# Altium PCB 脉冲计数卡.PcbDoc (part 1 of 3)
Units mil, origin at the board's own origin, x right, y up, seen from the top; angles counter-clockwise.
Board outline 5137.66 x 6771.53 mil, 4 copper layers (Top Layer, GND, VCC, Bottom Layer); 160 components, 225 nets, 1035 pads, 287 vias.
Unrouted connection lines stored in the file: 61.
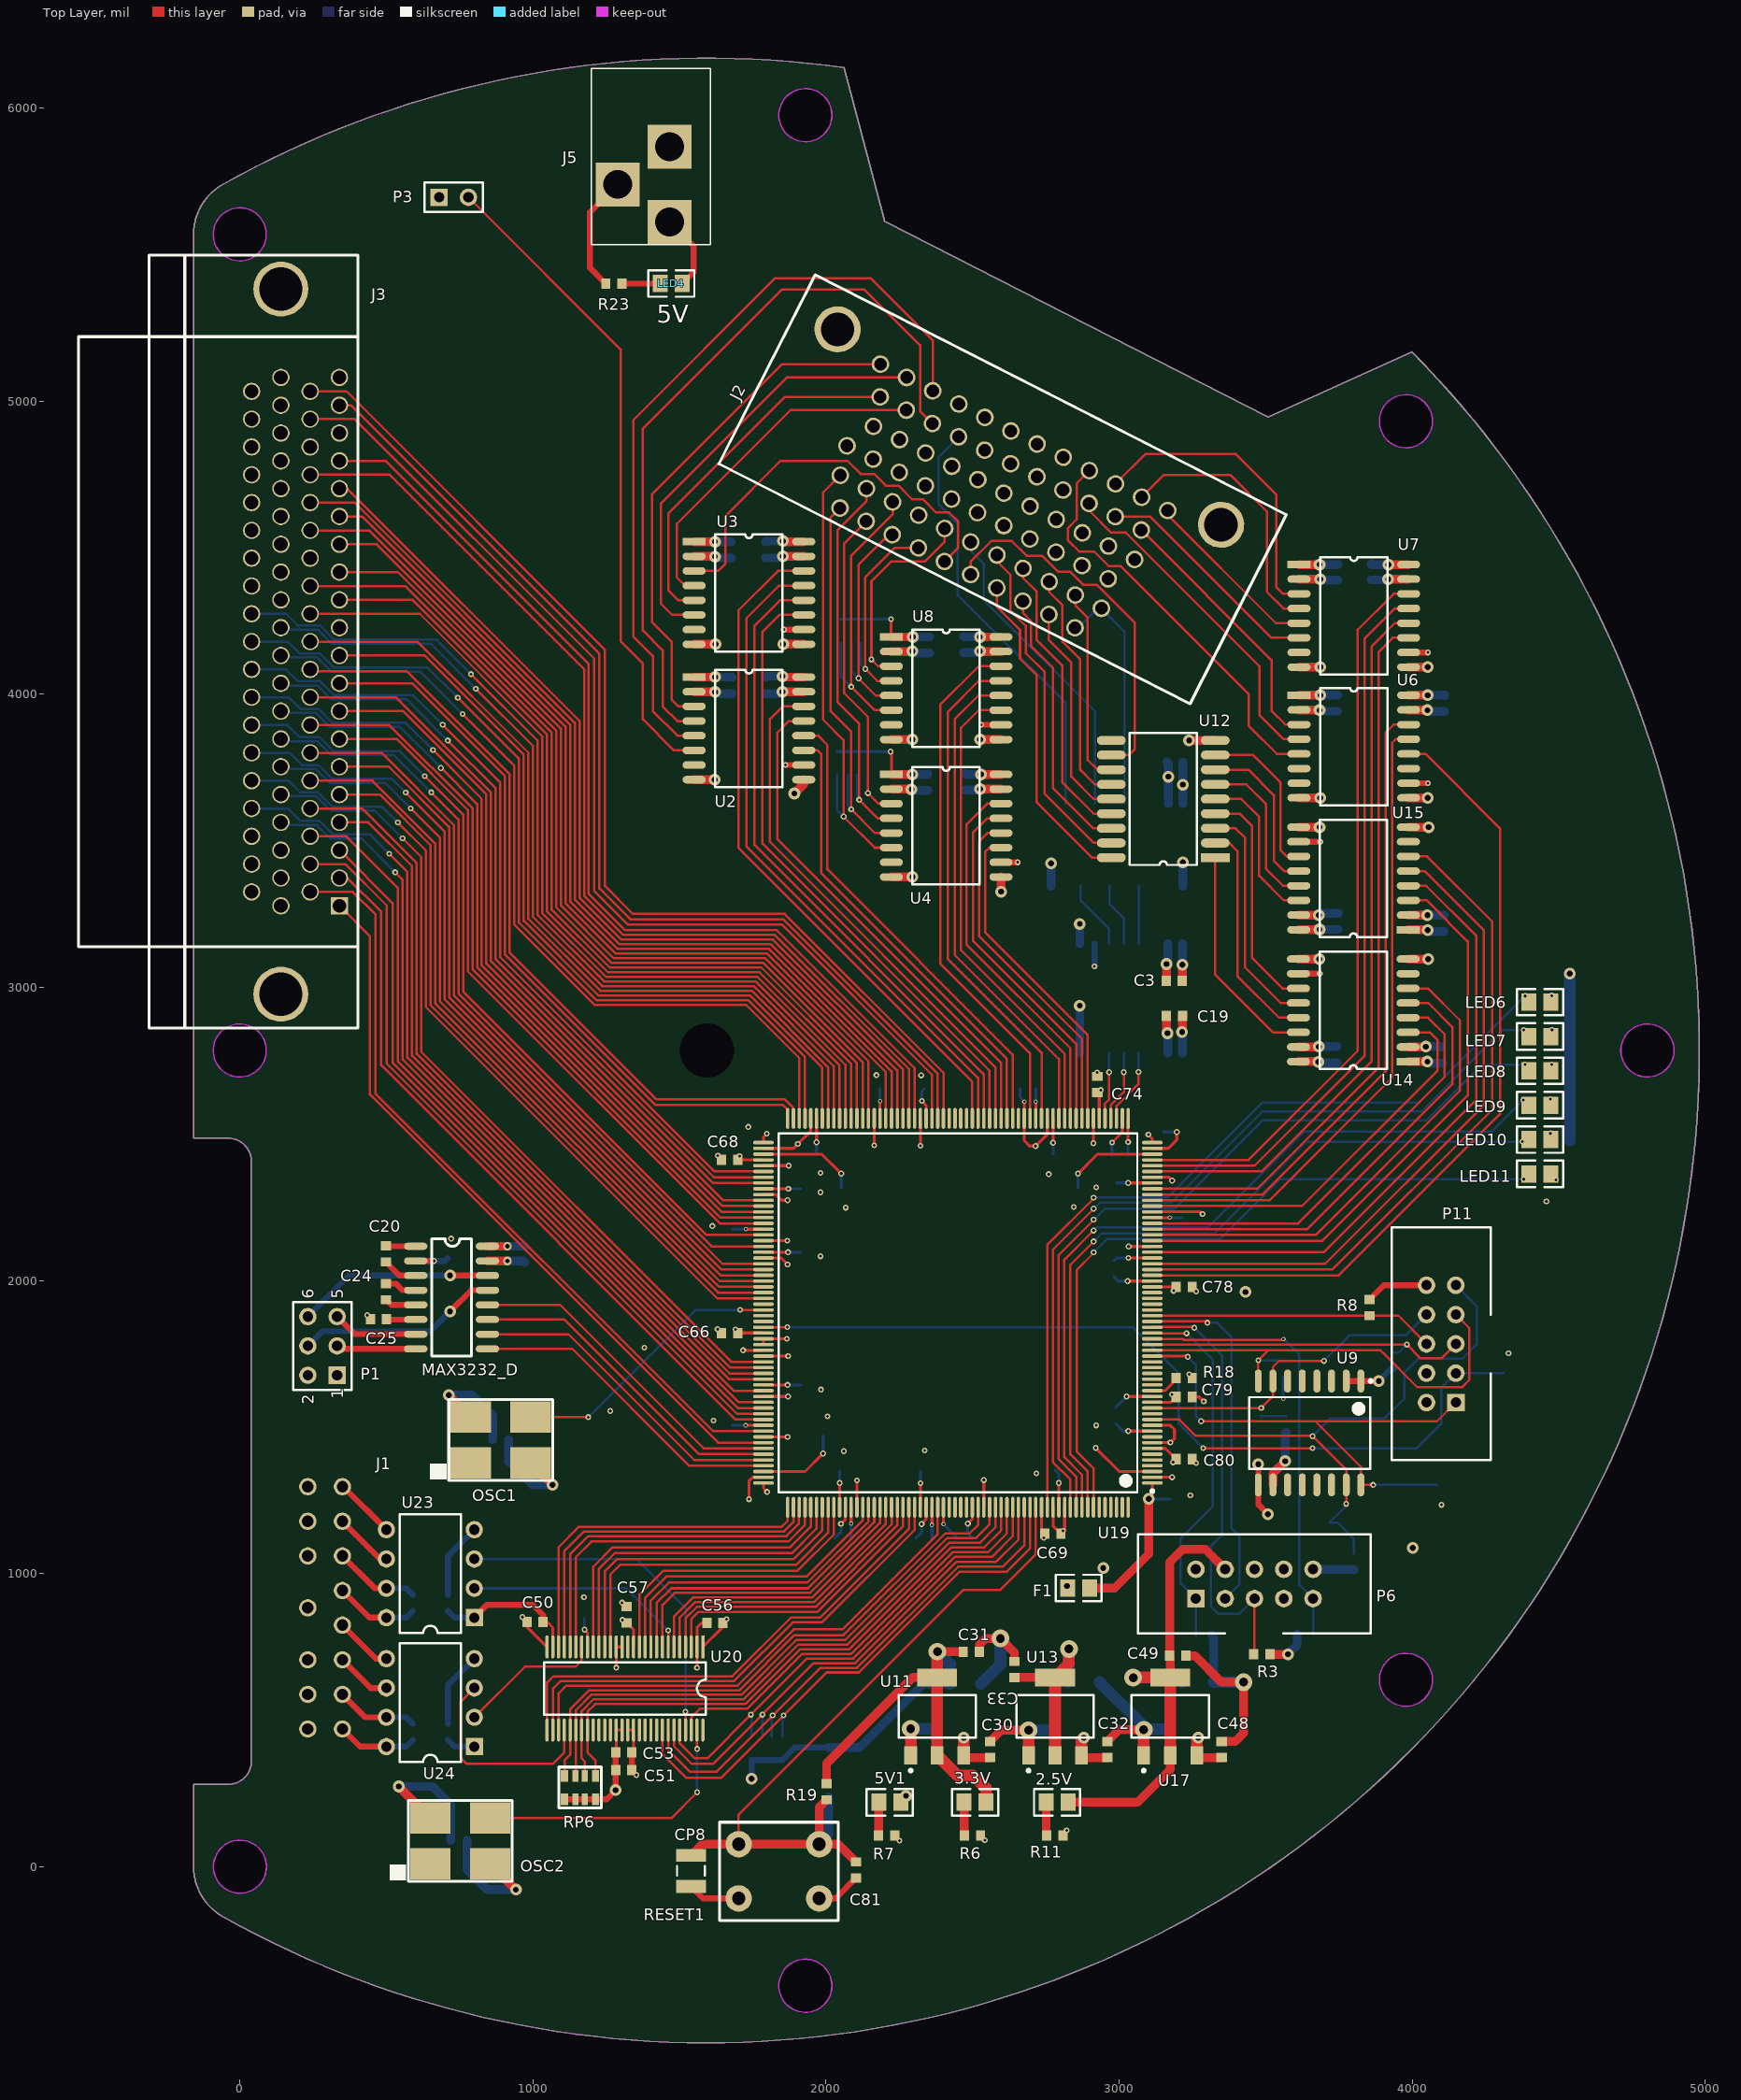
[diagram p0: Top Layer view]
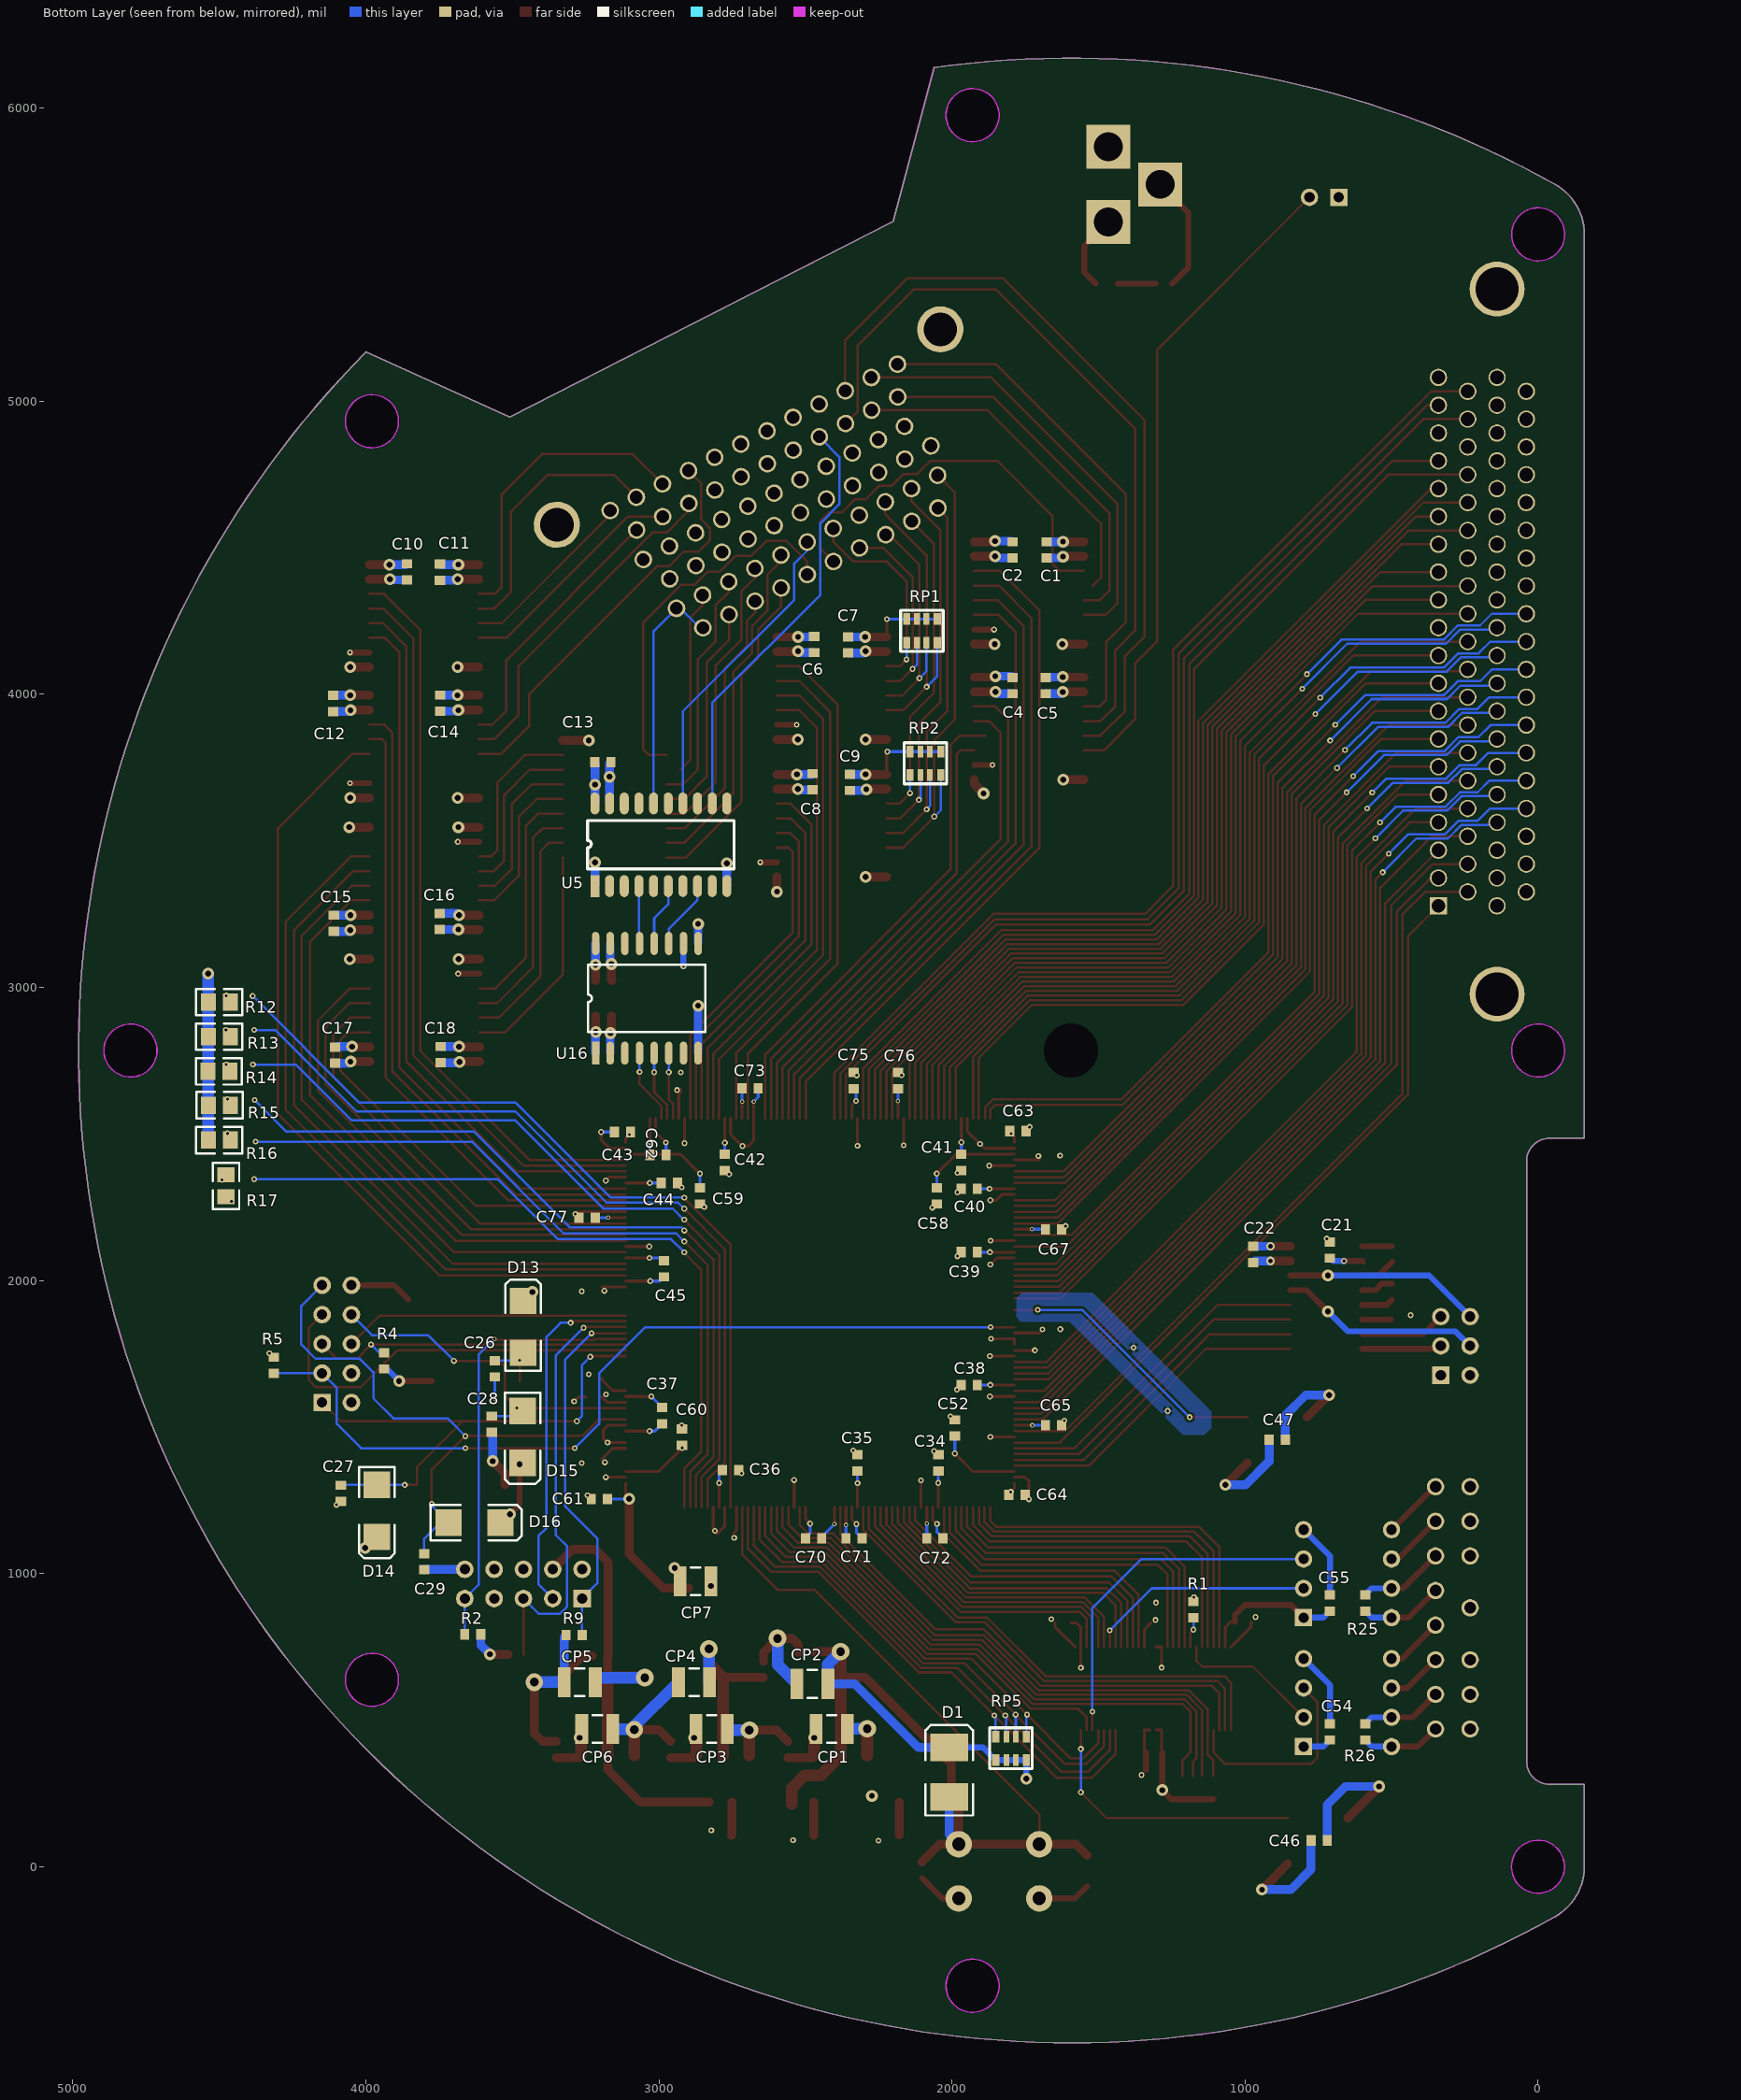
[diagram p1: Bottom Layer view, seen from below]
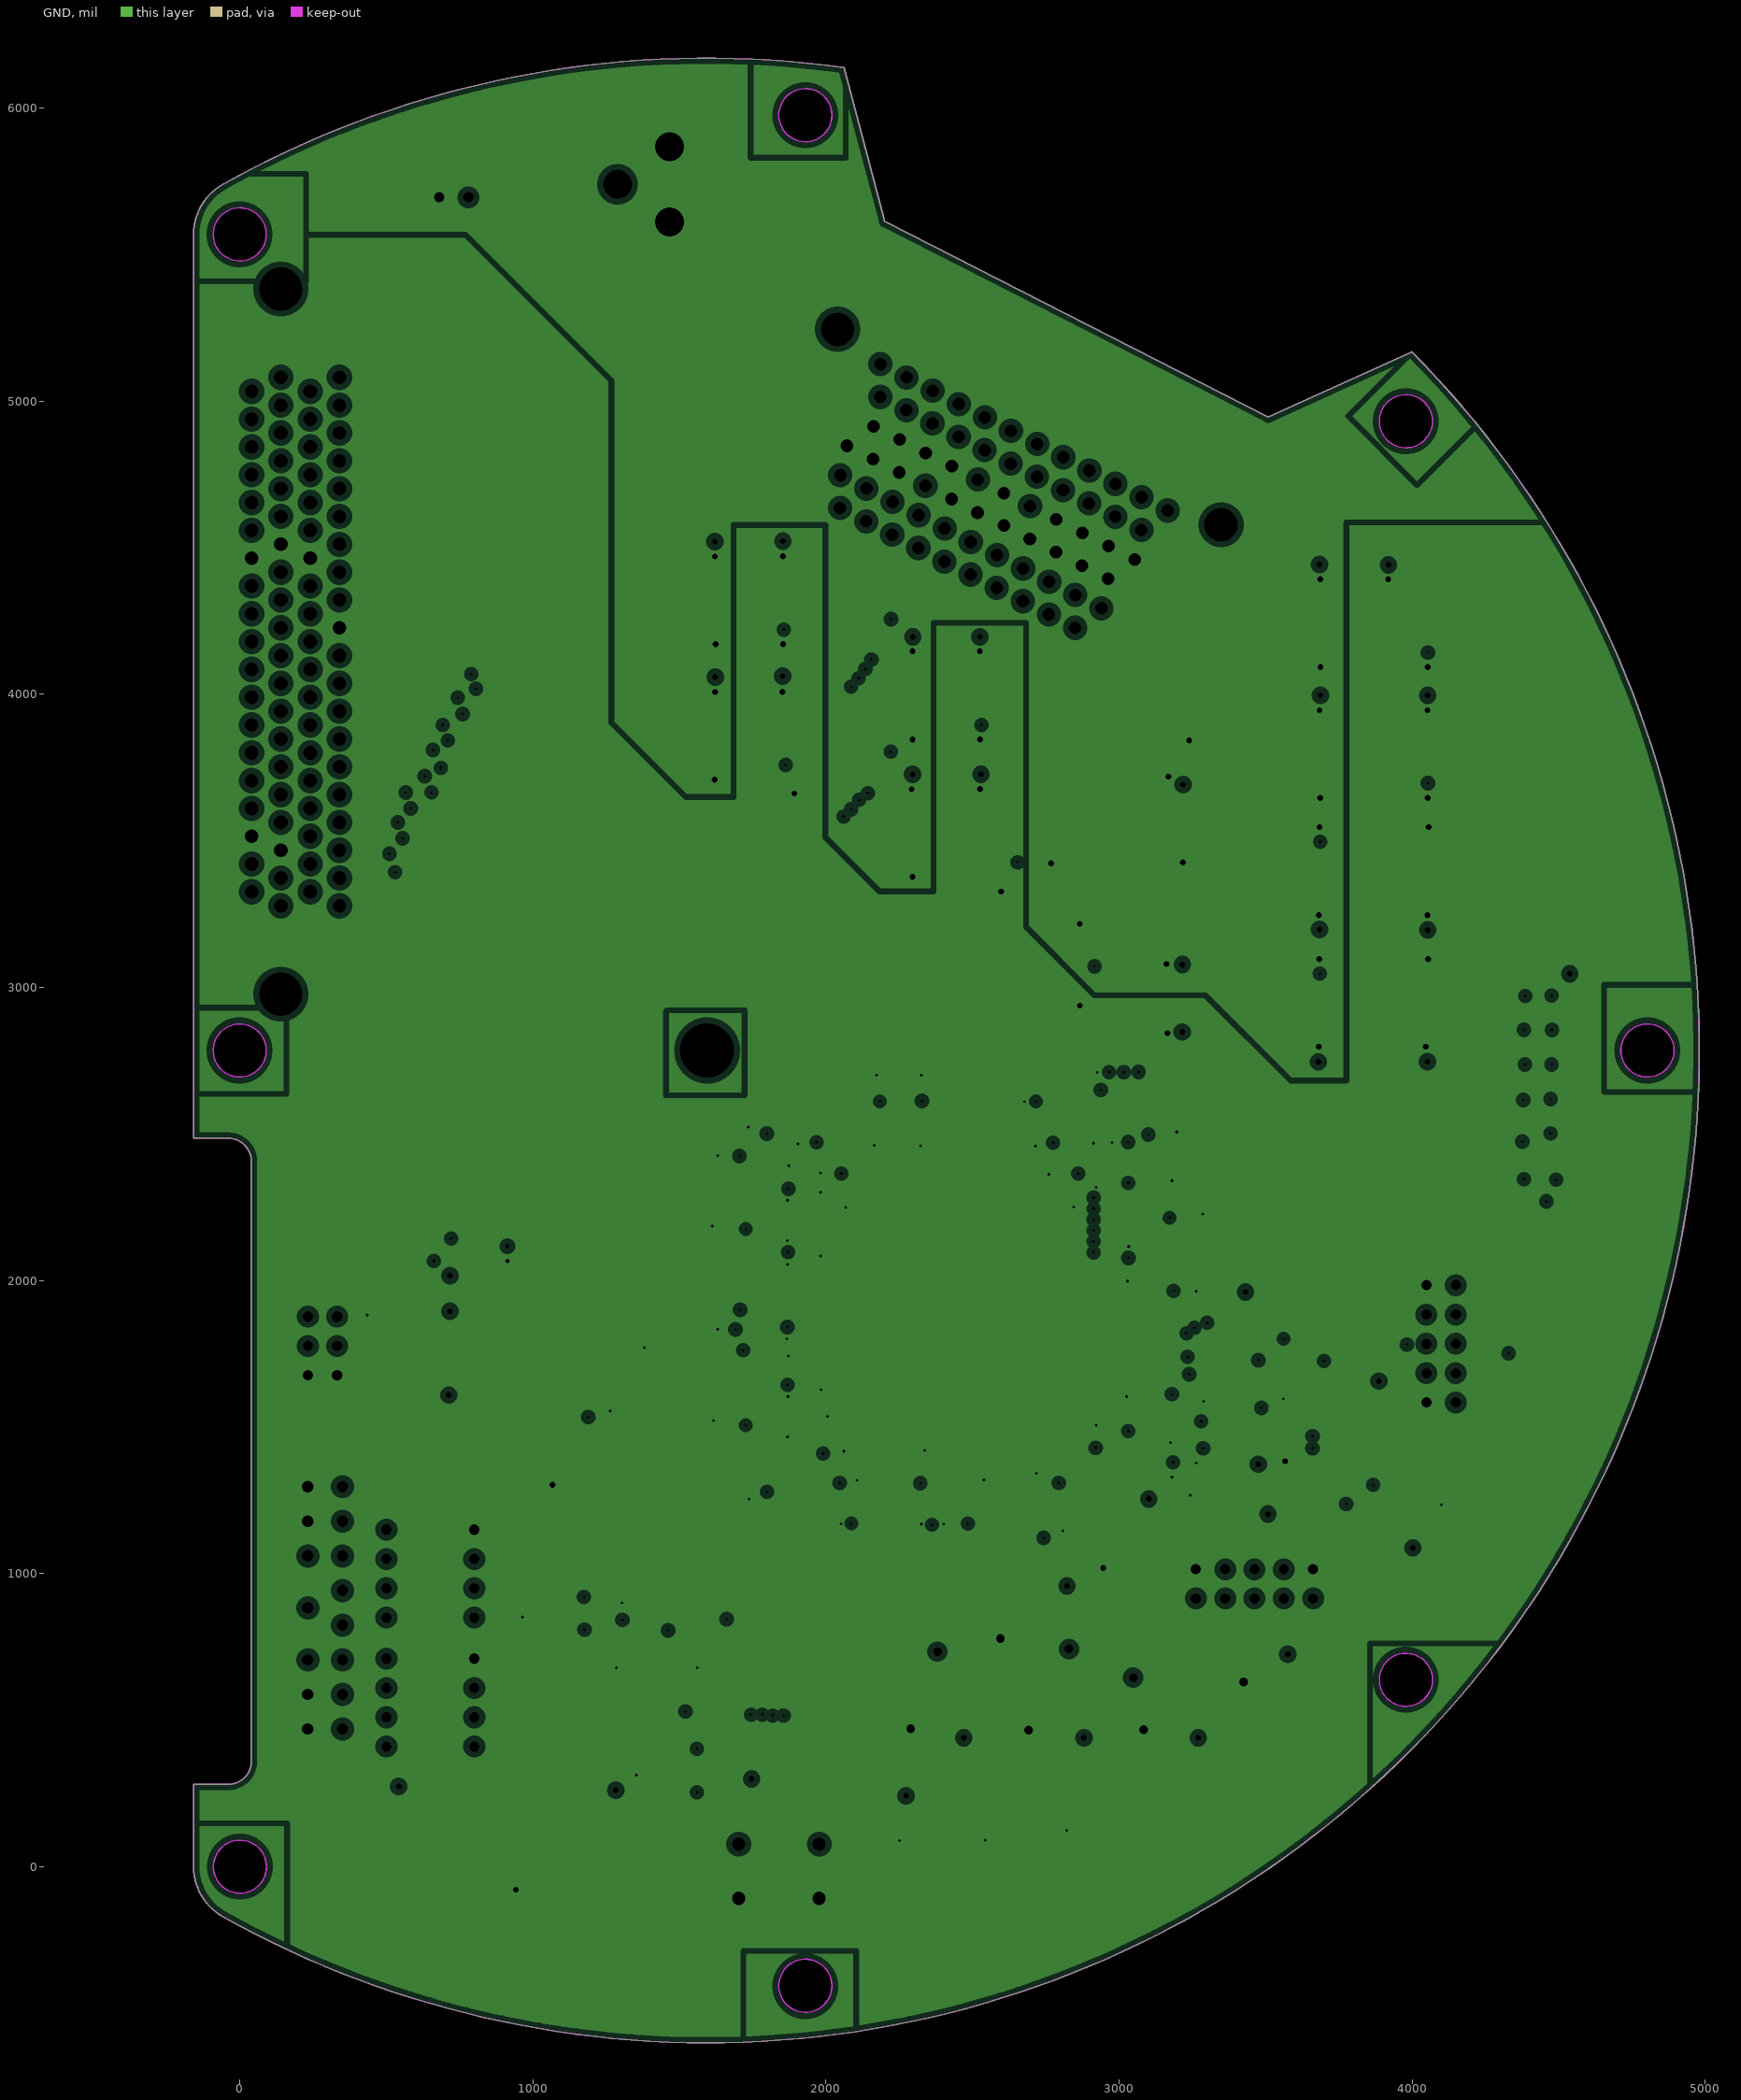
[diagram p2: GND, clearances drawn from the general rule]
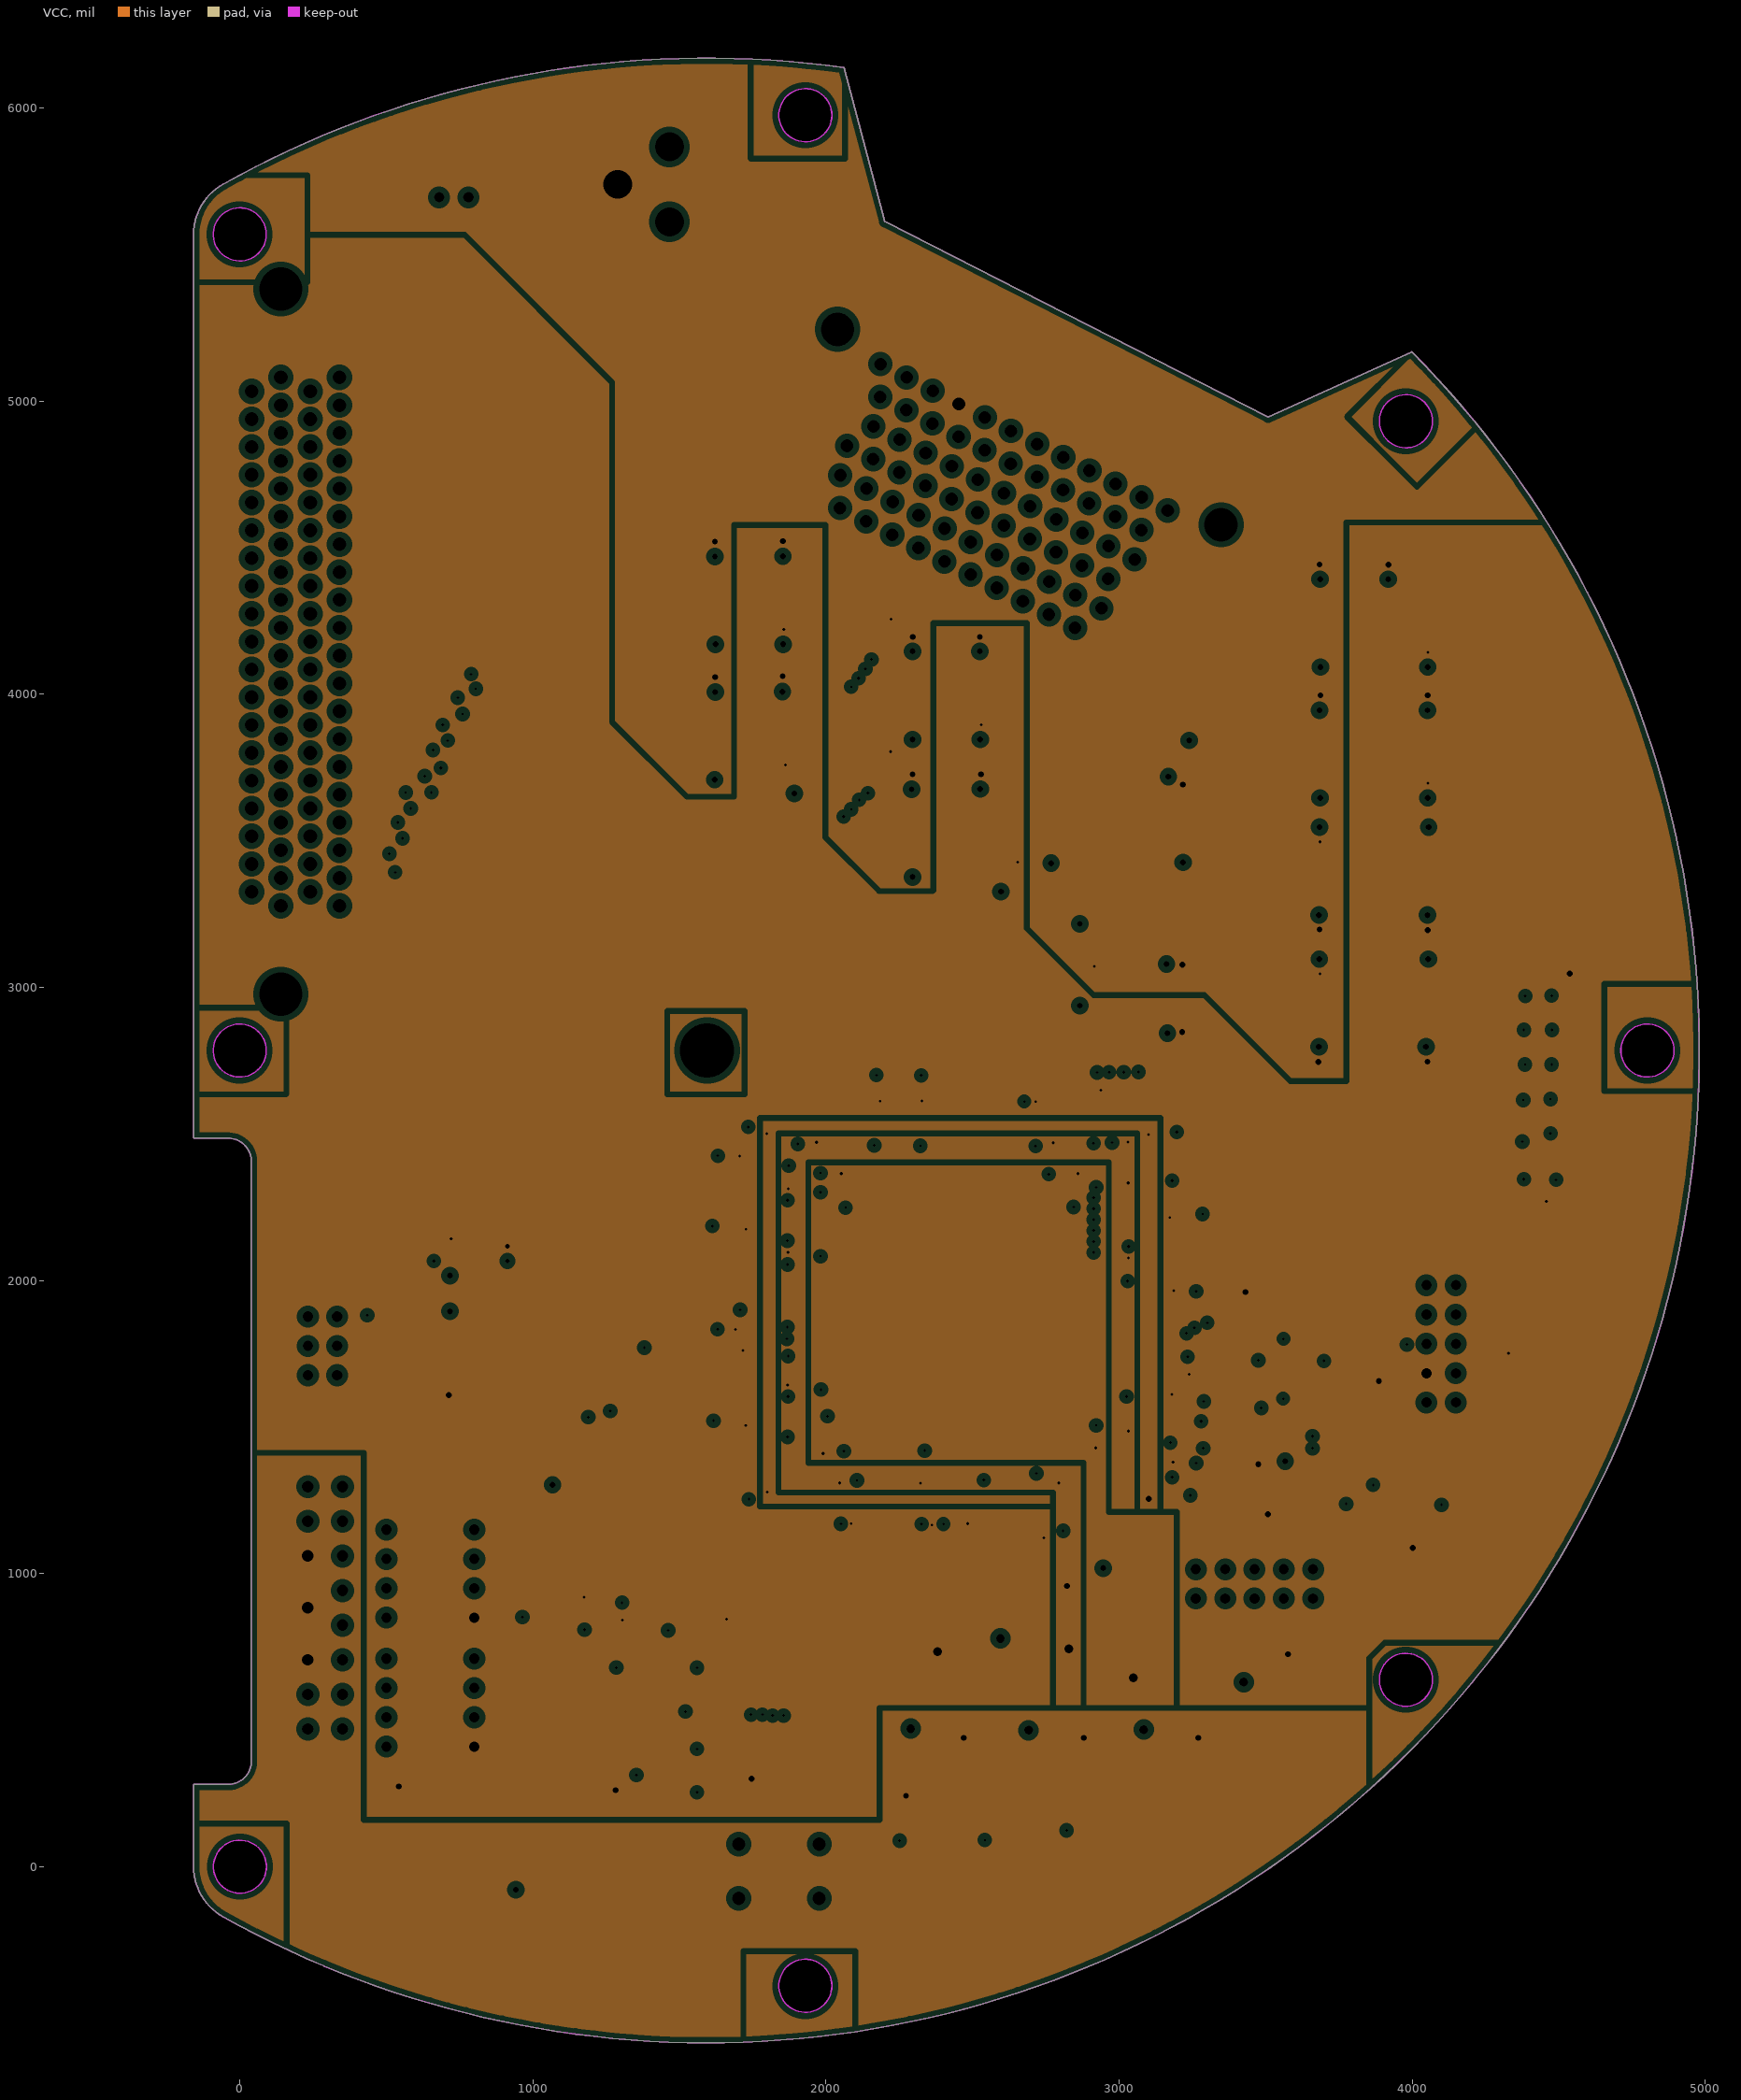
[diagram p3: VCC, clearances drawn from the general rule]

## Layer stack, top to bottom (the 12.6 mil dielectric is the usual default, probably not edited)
Top Layer: signal copper 1.4
Dielectric: core 12.6, FR-4, Dk 4.8
GND: plane copper 1.4, net (Multiple Nets)
Dielectric: prepreg 12.6, FR-4, Dk 4.8
VCC: plane copper 1.4, net (Multiple Nets)
Dielectric: core 12.6, FR-4, Dk 4.8
Bottom Layer: signal copper 1.4

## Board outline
-157.86,0.86 -157.86,281.01 -39.75,281.01 ccw(c-39.75,359.75) 38.99,359.75 38.99,2407 ccw(c-39.75,2407) -39.75,2485.74 -157.86,2485.74 -157.86,5569.05 cw(c38.99,5569.05) -57,5740.91 -57.03,5740.89 cw(c1594.11,2784.95) 2061.06,6138.43 2061,6138 2201.09,5613.19 2205.35,5610.72 3508.63,4946.67 3508.67,4946.74 3998,5168 3998.66,5168.65 cw(c1594.12,2784.95) -57.02,-170.99 -57,-171 cw(c38.99,0.86)

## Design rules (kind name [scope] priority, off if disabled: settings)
Clearance [All] p1: gap=5
Clearance Clearance_1 [All] p2: gap=7.87
ComponentClearance [All] p1: gap=0 collisioncheckmode=3 verticalgap=0 showdistances=FALSE
FabricationTestPointUsage TestPointUsage [All] p1: valid=0 allowmultiple=FALSE
FabricationTestpoint Testpoint [All] p1: side=3 testpointundercomponent=TRUE minsize=40 maxsize=100 preferedsize=60 minholesize=0 maxholesize=40 preferedholesize=32 testpointgrid=1 allowsidetop=TRUE allowsidebottom=TRUE usegrid=TRUE gridtolerance=0.01
HoleSize [All] p1: absolutevalues=TRUE maxlimit=200 minlimit=1 maxpercent=80.000 minpercent=20.000
PlaneClearance [All] p1: clearance=20
PlaneConnect [All] p1: planeconnectstyle=Direct reliefexpansion=20 reliefentries=4 reliefconductorwidth=10 reliefairgap=10
PolygonConnect [All] p1: connectstyle=Relief reliefconductorwidth=10 reliefentries=4 polygonreliefangle="90 Angle"
RoutingVias [All] p1: holewidth=23.62 width=39.37 viastyle="Through Hole" minholewidth=10 minwidth=20 maxholewidth=40 maxwidth=80
SilkscreenOverComponentPads [All] p1: minsilkscreentomaskgap=10
SolderMaskExpansion [All] p1: expansion=4
Width [All] p1: maxlimit=60 minlimit=5 preferedwidth=8
21 further rules are at their usual default settings.

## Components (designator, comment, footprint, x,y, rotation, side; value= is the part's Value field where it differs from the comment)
2.5V "LED12V" R2012-0805 2788.6,220 r180 top (schematic designator LED5)
3.3V "LED12V" R2012-0805 2508.6,220 r180 top (schematic designator LED2)
5V1 "LED12V" R2012-0805 2217.6,220 r180 top (schematic designator LED1)
C1 "0.1uF" 1608[0603] 1677,4493 r90 bottom
C2 "0.1uF" 1608[0603] 1793,4493 r90 bottom
C3 "0.1uF" 1608[0603] 3188,3023 r0 top
C4 "0.1uF" 1608[0603] 1793,4030 r90 bottom
C5 "0.1uF" 1608[0603] 1680,4030 r90 bottom
C6 "0.1uF" 1608[0603] 2470,4170 r90 bottom
C7 "0.1uF" 1608[0603] 2354,4169 r90 bottom
C8 "0.1uF" 1608[0603] 2475,3702 r90 bottom
C9 "0.1uF" 1608[0603] 2348,3700 r90 bottom
C10 "0.1uF" 1608[0603] 3860,4418 r90 bottom
C11 "0.1uF" 1608[0603] 3747,4417 r90 bottom
C12 "0.1uF" 1608[0603] 4111,3969 r90 bottom
C13 "0.1uF" 1608[0603] 3191,3769 r0 bottom
C14 "0.1uF" 1608[0603] 3746,3970 r90 bottom
C15 "0.1uF" 1608[0603] 4109,3219 r270 bottom
C16 "0.1uF" 1608[0603] 3748,3225 r270 bottom
C17 "0.1uF" 1608[0603] 4105,2769 r270 bottom
C18 "0.1uF" 1608[0603] 3744,2771 r270 bottom
C19 "0.1uF" 1608[0603] 3189,2903 r0 top
C20 "104" 1608[0603] 498,2091 r90 top
C21 "104" 1608[0603] 710,2104 r90 bottom
C22 "104" 1608[0603] 972,2089 r90 bottom
C24 "104" 1608[0603] 499,1962 r90 top
C25 "104" 1608[0603] 473,1868 r0 top
C26 "10pF" 1608[0603] 3560,1699 r90 bottom
C27 "10pF" 1608[0603] 4085,1274 r90 bottom
C28 "10pF" 1608[0603] 3570,1510 r90 bottom
C29 "10pF" 1608[0603] 3801,1041 r90 bottom
C30 "0.1uF" 1608[0603] 2560,400 r270 top
C31 "0.1uF" 1608[0603] 2496,733 r180 top
C32 "0.1uF" 1608[0603] 2960,400 r270 top
C33 "0.1uF" 1608[0603] 2643,673 r270 top
C34 "0.1uF" 1608[0603] 2046,1378 r270 bottom
C35 "0.1uF" 1608[0603] 2323,1378 r270 bottom
C36 "0.1uF" 1608[0603] 2755.12,1353 r0 bottom
C37 "0.1uF" 1608[0603] 2989,1539 r270 bottom
C38 "0.1uF" 1608[0603] 1941,1644 r180 bottom
C39 "0.1uF" 1608[0603] 1941,2097 r180 bottom
C40 "0.1uF" 1608[0603] 1941,2313 r180 bottom
C41 "0.1uF" 1608[0603] 1968,2403 r90 bottom
C42 "0.1uF" 1608[0603] 2775,2403 r90 bottom
C43 "0.1uF" 1608[0603] 3003,2428.59 r0 bottom
C44 "0.1uF" 1608[0603] 2964,2333 r0 bottom
C45 "0.1uF" 1608[0603] 2983,2040 r90 bottom
C46 "0.1uF" 1608[0603] 747,90 r0 bottom
C47 "0.1uF" 1608[0603] 890,1457 r0 bottom
C48 "0.1uF" 1608[0603] 3350,400 r270 top
C49 "0.1uF" 1608[0603] 3200,720 r180 top
C50 "0.1uF" 1608[0603] 1007,835 r0 top
C51 "0.1uF" 1608[0603] 1310,330 r180 top
C52 "0.1uF" 1608[0603] 1990,1497 r270 bottom
C53 "0.1uF" 1608[0603] 1310,390 r180 top
C54 "0.1uF" 1608[0603] 710,460 r90 bottom
C55 "0.1uF" 1608[0603] 710,900 r90 bottom
C56 "0.1uF" 1608[0603] 1621,832 r0 top
C57 "0.1uF" 1608[0603] 1320,860 r90 top
C58 "0.1uF" 1608[0603] 2052,2289 r90 bottom
C59 "0.1uF" 1608[0603] 2860,2289 r90 bottom
C60 "0.1uF" 1608[0603] 2921,1466 r270 bottom
C61 "0.1uF" 1608[0603] 3203,1254 r180 bottom
C62 "0.1uF" 1608[0603] 3124,2507 r180 bottom
C63 "0.1uF" 1608[0603] 1775,2510 r0 bottom
C64 "0.1uF" 1608[0603] 1778,1269 r0 bottom
C65 "0.1uF" 1608[0603] 1653,1506 r0 bottom
C66 "0.1uF" 1608[0603] 1671,1821 r0 top
C67 "0.1uF" 1608[0603] 1653,2175 r0 bottom
C68 "0.1uF" 1608[0603] 1671,2412 r0 top
C69 "0.1uF" 1608[0603] 2774,1136 r180 top
C70 "0.1uF" 1608[0603] 2472,1121 r0 bottom
C71 "0.1uF" 1608[0603] 2334,1121 r0 bottom
C72 "0.1uF" 1608[0603] 2058,1121 r0 bottom
C73 "0.1uF" 1608[0603] 2689,2656.41 r0 bottom
C74 "0.1uF" 1608[0603] 2926,2669 r270 top
C75 "0.1uF" 1608[0603] 2335,2682 r270 bottom
C76 "0.1uF" 1608[0603] 2184,2682 r270 bottom
C77 "0.1uF" 1608[0603] 3245,2214 r180 bottom
C78 "0.1uF" 1608[0603] 3222,1978 r180 top
C79 "0.1uF" 1608[0603] 3222,1603 r180 top
C80 "0.1uF" 1608[0603] 3222,1391 r180 top
C81 "0.1uF" 1608[0603] 2102,-11 r90 top
CP1 "10uF" C1210 2410,470 r180 bottom
CP2 "10uF" C1210 2476,624 r0 bottom
CP3 "10uF" C1210 2820,470 r180 bottom
CP4 "10uF" C1210 2880,630 r0 bottom
CP5 "10uF" C1210 3210,470 r180 bottom
CP6 "10uF" C1210 3270,630 r0 bottom
CP7 "22uF" C1210 2875,974 r0 bottom
CP8 "22uF" C1210 1539,-14 r270 top
D1 "Diode" DSO-C2/X3.3 2009,375 r90 bottom
D13 "D Schottky" SMB 3463,1842 r90 bottom
D14 "D Schottky" SMB 3962,1214 r270 bottom
D15 "D Schottky" SMB 3465,1467 r270 bottom
D16 "D Schottky" SMB 3629,1174 r180 bottom
F1 "Fuse" R2012-0805 2862,951 r180 top
J1 "J29J-15" J29J-15 350,470 r90 top locked
J2 "J30JZKW66" J30J-66ZKW2 2630,4787 r153 top locked
J3 "DB78" DB78 240,4180 r0 top locked
J5 "Header 3" POWER_CON 1466,5612 r90 top
LED4 "LED12V" R2012-0805 1472,5402 r0 top
LED6 "LED12V" R2012-0805 4436,2950 r180 top
LED7 "LED12V" R2012-0805 4436,2832.8 r180 top
LED8 "LED12V" R2012-0805 4436,2715.6 r180 top
LED9 "LED12V" R2012-0805 4436,2598.4 r180 top
LED10 "LED12V" R2012-0805 4436,2481.2 r180 top
LED11 "LED12V" R2012-0805 4436,2364 r180 top
MAX3232_D "SP3232E" SOJ-16_2 600,2117 r0 top locked
OSC1 "CRYSTAL  40M" OSC 788,1378 r0 top
OSC2 "CRYSTAL  32M" OSC 650,10 r0 top
P1 "Header 3X2" HDR2X3 332,1677 r90 top locked
P3 "Header 2" HDR1X2 680,5696 r0 top locked
P6 "Header 5X2" FPGA_LOAD 3262,915 r0 top locked
P11 "Header 5X2" FPGA_LOAD 4149,1584 r90 top locked
R1 "10K" 1608[0603] 1176,877 r270 bottom
R2 "10K" 1608[0603] 3635,793 r180 bottom
R3 "10K" 1608[0603] 3487,725 r0 top
R4 "10K" 1608[0603] 3937,1726 r270 bottom
R5 "10K" 1608[0603] 4314,1711 r90 bottom
R6 "1K" 1608[0603] 2499.6,107 r0 top
R7 "1K" 1608[0603] 2206.6,107 r0 top
R8 "10K" 1608[0603] 3855,1908 r270 top
R9 "1K" 1608[0603] 3289,790 r180 bottom
R11 "1K" 1608[0603] 2780.6,107 r0 top
R12 "1K" R2012-0805 4500,2950 r0 bottom
R13 "1K" R2012-0805 4500,2832 r0 bottom
R14 "1K" R2012-0805 4501,2714 r0 bottom
R15 "1K" R2012-0805 4499,2598 r0 bottom
R16 "1K" R2012-0805 4500,2479 r0 bottom
R17 "1K" R2012-0805 4477,2323 r270 bottom
R18 "10K" 1608[0603] 3222,1668 r180 top
R19 "1K" 1608[0603] 2002,256 r90 top
R23 "1K" 1608[0603] 1276,5401 r180 top
R25 "120" 1608[0603] 590,900 r90 bottom
R26 "120" 1608[0603] 590,460 r90 bottom
RESET1 "SW" SW4 1702,-8 r90 top
RP1 "1K" RP8 2055,4257 r270 bottom
RP2 "1K" RP8 2043,3805 r270 bottom
RP5 "470" RP8 1846,364 r90 bottom
RP6 "470" RP8 1113,230 r90 top
U2 "SI4880" RW-16 1550,4059 r0 top locked
U3 "SI4880" RW-16 1550,4521 r0 top locked
U4 "SI4880" RW-16 2223,3727 r0 top locked
U5 "SN74ABT244AN" SN74ABT244ADW--SOIC20 3218,3287 r90 bottom locked
U6 "SI4880" RW-16 3614,3997 r0 top locked
U7 "SI4880" RW-16 3614,4443 r0 top locked
U8 "SI4880" RW-16 2223,4196 r0 top locked
U9 "EPCS16SI16N" SOIC16_L 3650,1480 r270 top locked
U11 "REG1117" ZZ311 2289,380 r0 top locked
U12 "ULN2803" ULN2803AFWG--SOIC18 3328,3443 r180 top locked
U13 "REG1117" ZZ311 2691,380 r0 top locked
U14 "SI4880" RW-16 3986,2747 r180 top locked
U15 "SI4880" RW-16 3987,3197 r180 top locked
U16 "SI4880" RW-16 3216,2776 r90 bottom locked
U17 "REG1117" ZZ311 3084,380 r0 top locked
U19 "EP3C16Q240C8N" PQFP240_N 2450,1890 r180 top locked
U20 "SC28L202A1DGG" TSSOP56 1580,750 r270 top
U23 "MAX3077EESA" DIP8 650,1000 r90 top locked
U24 "MAX3077EESA" DIP8 650,560 r90 top locked

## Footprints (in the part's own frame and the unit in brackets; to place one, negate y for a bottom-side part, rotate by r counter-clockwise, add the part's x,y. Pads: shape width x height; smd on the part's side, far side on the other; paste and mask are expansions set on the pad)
1608[0603] [mm]
  rect 0.8x0.9 smd: 1(-0.7,0) 2(0.7,0)
  body extent -0.87,-0.48 0.87,0.48, height 1.3
C1210 [mm]
  rect 1.1x2.6 smd: 1(-1.35,0) 2(1.35,0)
  silkscreen extent -0.4,-1.2 0.4,1.2, body extent -1.7,-1.35 1.7,1.35, height 1.3
DB78 [mm]
  rect 1.5x1.5 hole 1.19: 1(2.54,-22.895)
  round 1.5 hole 1.19: 2(0,-21.69) 3(2.54,-20.485) 4(0,-19.28) 5(2.54,-18.075) 6(0,-16.87) 7(2.54,-15.665) 8(0,-14.46) 9(2.54,-13.255) 10(0,-12.05) 11(2.54,-10.845) 12(0,-9.64) 13(2.54,-8.435) 14(0,-7.23) 15(2.54,-6.025) 16(0,-4.82) 17(2.54,-3.615) 18(0,-2.41) 19(2.54,-1.205) 20(0,0) 21(2.54,1.205) 22(0,2.41) 23(2.54,3.615) 24(0,4.82) 25(2.54,6.025) 26(0,7.23) 27(2.54,8.435) 28(0,9.64) 29(2.54,10.845) 30(0,12.05) 31(2.54,13.255) 32(0,14.46) 33(2.54,15.665) 34(0,16.87) 35(2.54,18.075) 36(0,19.28) 37(2.54,20.485) 38(0,21.69) 39(2.54,22.895) 40(-2.54,22.895) 41(-5.08,21.69) 42(-2.54,20.485) 43(-5.08,19.28) 44(-2.54,18.075) 45(-5.08,16.87) 46(-2.54,15.665) 47(-5.08,14.46) 48(-2.54,13.255) 49(-5.08,12.05) 50(-2.54,10.845) 51(-5.08,9.64) 52(-2.54,8.435) 53(-5.08,7.23) 54(-2.54,6.025) 55(-5.08,4.82) 56(-2.54,3.615) 57(-5.08,2.41) 58(-2.54,1.205) 59(-5.08,0) 60(-2.54,-1.205) 61(-5.08,-2.41) 62(-2.54,-3.615) 63(-5.08,-4.82) 64(-2.54,-6.025) 65(-5.08,-7.23) 66(-2.54,-8.435) 67(-5.08,-9.64) 68(-2.54,-10.845) 69(-5.08,-12.05) 70(-2.54,-13.255) 71(-5.08,-14.46) 72(-2.54,-15.665) 73(-5.08,-16.87) 74(-2.54,-18.075) 75(-5.08,-19.28) 76(-2.54,-20.485) 77(-5.08,-21.69) 78(-2.54,-22.895)
  round 4.76 hole 3.75: 79(-2.54,-30.555) 80(-2.54,30.555)
  silkscreen extent -20.07,-33.5 4.13,33.5
DIP8 [mm]
  rect 1.5x1.5 hole 0.9: 1(-3.81,-3.81)
  round 1.5 hole 0.9: 2(-1.27,-3.81) 3(1.27,-3.81) 4(3.81,-3.81) 5(3.81,3.81) 6(1.27,3.81) 7(-1.27,3.81) 8(-3.81,3.81)
  silkscreen extent -5.15,-2.65 5.15,2.65
DSO-C2/X3.3 [mm]
  rect 2.4x3.3 smd: 1(-3.475,0.006) 2(0.808,0.006)
  silkscreen extent -5.07,-2.04 2.76,2.06
FPGA_LOAD [mil]
  rect 60x60 hole 35: 1(0,0)
  round 60 hole 35: 2(0,100) 3(100,0) 4(100,100) 5(200,0) 6(200,100) 7(300,0) 8(300,100) 9(400,0) 10(400,100)
  silkscreen extent -197,-119 597,219
HDR1X2 [mm]
  rect 1.5x1.5 hole 0.9: 1(0,0)
  round 1.5 hole 0.9: 2(2.54,0)
  silkscreen extent -1.27,-1.27 3.81,1.27
HDR2X3 [mm] "Connector; Header; 3x2 Position"
  rect 1.5x1.5 hole 0.9: 1(0,0)
  round 1.5 hole 0.9: 2(0,2.54) 3(2.54,0) 4(2.54,2.54) 5(5.08,0) 6(5.08,2.54)
  silkscreen extent -1.27,-1.27 6.35,3.81
J29J-15 [mm]
  round 1.5 hole 1: 1(0,0) 2(3,0) 3(6,0) 4(9,0) 5(12,0) 6(15,0) 7(18,0) 8(21,0) 9(0,3) 10(3,3) 11(6,3) 12(10.5,3) 13(15,3) 14(18,3) 15(21,3)
J30J-66ZKW2 [mil]
  round 60 hole 43.31: 1(-550,-101) 2(-500,-1) 3(-450,-101) 4(-400,-1) 5(-350,-101) 6(-300,-1) 7(-250,-101) 8(-200,-1) 9(-150,-101) 10(-100,-1) 11(-50,-101) 12(0,0) 13(50,-100) 14(100,-1) 15(150,-101) 16(200,-1) 17(250,-101) 18(300,-1) 19(350,-101) 20(400,-1) 21(450,-101) 22(500,-1) 23(550,-101) 24(-525,99) 25(-475,199) 26(-425,99) 27(-375,199) 28(-325,99) 29(-275,199) 30(-225,99) 31(-175,199) 32(-125,99) 33(-75,199) 34(-25,100) 35(25,200) 36(75,99) 37(125,199) 38(175,99) 39(225,199) 40(275,99) 41(325,199) 42(375,99) 43(425,199) 44(475,99) 45(525,199) 46(-500,299) 47(-450,399) 48(-400,299) 49(-350,399) 50(-300,299) 51(-250,399) 52(-200,299) 53(-150,399) 54(-100,299) 55(-50,399) 56(0,300) 57(50,400) 58(100,299) 59(150,399) 60(200,299) 61(250,399) 62(300,299) 63(350,399) 64(400,299) 65(450,399) 66(500,299)
  round 157.48 hole 114.17: 67(-734.25,-140.37) 68(734.25,-140.37)
  silkscreen extent -917,-272 887,452
OSC [mm]
  rect 3.5x2.7 smd: 1(0,0) 2(5.182,0) 3(5.182,3.962) 4(0,3.962)
  silkscreen extent -3.53,-1.51 7.1,5.49
POWER_CON [mm]
  rect 3.8x3.8 hole 2.5: 1(0,0) 2(6.5,0) 3(3.25,4.5)
  silkscreen extent -1.98,-3.56 13.31,6.78
PQFP240_N [mm]
  oval 1.8x0.3 smd: 1(-16.85,14.75) 2(-16.85,14.25) 3(-16.85,13.75) 4(-16.85,13.25) 5(-16.85,12.75) 6(-16.85,12.25) 7(-16.85,11.75) 8(-16.85,11.25) 9(-16.85,10.75) 10(-16.85,10.25) 11(-16.85,9.75) 12(-16.85,9.25) 13(-16.85,8.75) 14(-16.85,8.25) 15(-16.85,7.75) 16(-16.85,7.25) 17(-16.85,6.75) 18(-16.85,6.25) 19(-16.85,5.75) 20(-16.85,5.25) 21(-16.85,4.75) 22(-16.85,4.25) 23(-16.85,3.75) 24(-16.85,3.25) 25(-16.85,2.75) 26(-16.85,2.25) 27(-16.85,1.75) 28(-16.85,1.25) 29(-16.85,0.75) 30(-16.85,0.25) 31(-16.85,-0.25) 32(-16.85,-0.75) 33(-16.85,-1.25) 34(-16.85,-1.75) 35(-16.85,-2.25) 36(-16.85,-2.75) 37(-16.85,-3.25) 38(-16.85,-3.75) 39(-16.85,-4.25) 40(-16.85,-4.75) 41(-16.85,-5.25) 42(-16.85,-5.75) 43(-16.85,-6.25) 44(-16.85,-6.75) 45(-16.85,-7.25) 46(-16.85,-7.75) 47(-16.85,-8.25) 48(-16.85,-8.75) 49(-16.85,-9.25) 50(-16.85,-9.75) 51(-16.85,-10.25) 52(-16.85,-10.75) 53(-16.85,-11.25) 54(-16.85,-11.75) 55(-16.85,-12.25) 56(-16.85,-12.75) 57(-16.85,-13.25) 58(-16.85,-13.75) 59(-16.85,-14.25) 60(-16.85,-14.75) 121(16.85,-14.75) 122(16.85,-14.25) 123(16.85,-13.75) 124(16.85,-13.25) 125(16.85,-12.75) 126(16.85,-12.25) 127(16.85,-11.75) 128(16.85,-11.25) 129(16.85,-10.75) 130(16.85,-10.25) 131(16.85,-9.75) 132(16.85,-9.25) 133(16.85,-8.75) 134(16.85,-8.25) 135(16.85,-7.75) 136(16.85,-7.25) 137(16.85,-6.75) 138(16.85,-6.25) 139(16.85,-5.75) 140(16.85,-5.25) 141(16.85,-4.75) 142(16.85,-4.25) 143(16.85,-3.75) 144(16.85,-3.25) 145(16.85,-2.75) 146(16.85,-2.25) 147(16.85,-1.75) 148(16.85,-1.25) 149(16.85,-0.75) 150(16.85,-0.25) 151(16.85,0.25) 152(16.85,0.75) 153(16.85,1.25) 154(16.85,1.75) 155(16.85,2.25) 156(16.85,2.75) 157(16.85,3.25) 158(16.85,3.75) 159(16.85,4.25) 160(16.85,4.75) 161(16.85,5.25) 162(16.85,5.75) 163(16.85,6.25) 164(16.85,6.75) 165(16.85,7.25) 166(16.85,7.75) 167(16.85,8.25) 168(16.85,8.75) 169(16.85,9.25) 170(16.85,9.75) 171(16.85,10.25) 172(16.85,10.75) 173(16.85,11.25) 174(16.85,11.75) 175(16.85,12.25) 176(16.85,12.75) 177(16.85,13.25) 178(16.85,13.75) 179(16.85,14.25) 180(16.85,14.75)
  oval 0.3x1.8 smd: 61(-14.75,-16.85) 62(-14.25,-16.85) 63(-13.75,-16.85) 64(-13.25,-16.85) 65(-12.75,-16.85) 66(-12.25,-16.85) 67(-11.75,-16.85) 68(-11.25,-16.85) 69(-10.75,-16.85) 70(-10.25,-16.85) 71(-9.75,-16.85) 72(-9.25,-16.85) 73(-8.75,-16.85) 74(-8.25,-16.85) 75(-7.75,-16.85) 76(-7.25,-16.85) 77(-6.75,-16.85) 78(-6.25,-16.85) 79(-5.75,-16.85) 80(-5.25,-16.85) 81(-4.75,-16.85) 82(-4.25,-16.85) 83(-3.75,-16.85) 84(-3.25,-16.85) 85(-2.75,-16.85) 86(-2.25,-16.85) 87(-1.75,-16.85) 88(-1.25,-16.85) 89(-0.75,-16.85) 90(-0.25,-16.85) 91(0.25,-16.85) 92(0.75,-16.85) 93(1.25,-16.85) 94(1.75,-16.85) 95(2.25,-16.85) 96(2.75,-16.85) 97(3.25,-16.85) 98(3.75,-16.85) 99(4.25,-16.85) 100(4.75,-16.85) 101(5.25,-16.85) 102(5.75,-16.85) 103(6.25,-16.85) 104(6.75,-16.85) 105(7.25,-16.85) 106(7.75,-16.85) 107(8.25,-16.85) 108(8.75,-16.85) 109(9.25,-16.85) 110(9.75,-16.85) 111(10.25,-16.85) 112(10.75,-16.85) 113(11.25,-16.85) 114(11.75,-16.85) 115(12.25,-16.85) 116(12.75,-16.85) 117(13.25,-16.85) 118(13.75,-16.85) 119(14.25,-16.85) 120(14.75,-16.85) 181(14.75,16.85) 182(14.25,16.85) 183(13.75,16.85) 184(13.25,16.85) 185(12.75,16.85) 186(12.25,16.85) 187(11.75,16.85) 188(11.25,16.85) 189(10.75,16.85) 190(10.25,16.85) 191(9.75,16.85) 192(9.25,16.85) 193(8.75,16.85) 194(8.25,16.85) 195(7.75,16.85) 196(7.25,16.85) 197(6.75,16.85) 198(6.25,16.85) 199(5.75,16.85) 200(5.25,16.85) 201(4.75,16.85) 202(4.25,16.85) 203(3.75,16.85) 204(3.25,16.85) 205(2.75,16.85) 206(2.25,16.85) 207(1.75,16.85) 208(1.25,16.85) 209(0.75,16.85) 210(0.25,16.85) 211(-0.25,16.85) 212(-0.75,16.85) 213(-1.25,16.85) 214(-1.75,16.85) 215(-2.25,16.85) 216(-2.75,16.85) 217(-3.25,16.85) 218(-3.75,16.85) 219(-4.25,16.85) 220(-4.75,16.85) 221(-5.25,16.85) 222(-5.75,16.85) 223(-6.25,16.85) 224(-6.75,16.85) 225(-7.25,16.85) 226(-7.75,16.85) 227(-8.25,16.85) 228(-8.75,16.85) 229(-9.25,16.85) 230(-9.75,16.85) 231(-10.25,16.85) 232(-10.75,16.85) 233(-11.25,16.85) 234(-11.75,16.85) 235(-12.25,16.85) 236(-12.75,16.85) 237(-13.25,16.85) 238(-13.75,16.85) 239(-14.25,16.85) 240(-14.75,16.85)
  silkscreen extent -16.98,-15.55 15.55,15.57, body extent -16,-16 16,16, height 4.1
R2012-0805 [mm]
  rect 1.3x1.5 smd: 1(-0.95,0) 2(0.95,0)
  silkscreen extent -2,-1.15 2,1.15
RP8 [mil]
  rect 40x25 smd: 1(0.29,5) 8(80.29,5)
  rect 40x20 smd: 2(0.29,-32) 3(0.29,-64) 6(80.29,-64) 7(80.29,-32)
  rect 40x24 smd: 4(0.29,-100) 5(80.29,-100)
  silkscreen extent -30,-120 110,25
RW-16 [mm]
  rect 2x0.65 smd: 1(0,0)
  oval 2x0.65 smd: 2(0,-1.27) 3(0,-2.54) 4(0,-3.81) 5(0,-5.08) 6(0,-6.35) 7(0,-7.62) 8(0,-8.89) 9(9.5,-8.89) 10(9.5,-7.62) 11(9.5,-6.35) 12(9.5,-5.08) 13(9.5,-3.81) 14(9.5,-2.54) 15(9.5,-1.27) 16(9.5,0)
  silkscreen extent 1.84,-9.53 7.66,0.64
SMB [mm]
  rect 2.3x2.3 smd: 1(-2.25,0) 2(2.25,0)
  silkscreen extent -3.8,-1.55 4.1,1.55
SN74ABT244ADW--SOIC20 [mm]
  rect 1.9x0.773 smd: 1(1.5,0)
  oval 1.9x0.773 smd: 2(1.5,-1.27) 3(1.5,-2.54) 4(1.5,-3.81) 5(1.5,-5.08) 6(1.5,-6.35) 7(1.5,-7.62) 8(1.5,-8.89) 9(1.5,-10.16) 10(1.5,-11.43) 11(8.66,-11.43) 12(8.66,-10.16) 13(8.66,-8.89) 14(8.66,-7.62) 15(8.66,-6.35) 16(8.66,-5.08) 17(8.66,-3.81) 18(8.66,-2.54) 19(8.66,-1.27) 20(8.66,0)
  silkscreen extent 2.98,-12.06 7.17,0.63
SOIC16_L [mm]
  oval 2x0.6 smd: 1(-4.5,4.445) 2(-4.5,3.175) 3(-4.5,1.905) 4(-4.5,0.635) 5(-4.5,-0.635) 6(-4.5,-1.905) 7(-4.5,-3.175) 8(-4.5,-4.445) 9(4.5,-4.445) 10(4.5,-3.175) 11(4.5,-1.905) 12(4.5,-0.635) 13(4.5,0.635) 14(4.5,1.905) 15(4.5,3.175) 16(4.5,4.445)
  silkscreen extent -4.62,-5.25 3.1,5.42, body extent -3.75,-5.25 3.75,5.25, height 2.65
SOJ-16_2 [mil]
  oval 80x24 smd: 1(0,0) 2(0,-50) 3(0,-100) 4(0,-150) 5(0,-200) 6(0,-250) 7(0,-300) 8(0,-350) 9(245,-350) 10(245,-300) 11(245,-250) 12(245,-200) 13(245,-150) 14(245,-100) 15(245,-50) 16(245,0)
  silkscreen extent 55,-375 190,25
SW4 [mil]
  round 90 hole 45: 1(-100,0) 1(-100,-275) 2(85,0) 2(85,-275)
  silkscreen extent -175,-340 160,65
TSSOP56 [mm]
  rect 2x0.28 smd: 1(-0.003,-0.01)
  oval 2x0.28 smd: 2(-0.003,-0.51) 3(-0.003,-1.01) 4(-0.003,-1.51) 5(-0.003,-2.01) 6(-0.003,-2.51) 7(-0.003,-3.01) 8(-0.003,-3.51) 9(-0.003,-4.01) 10(-0.003,-4.51) 11(-0.003,-5.01) 12(-0.003,-5.51) 13(-0.003,-6.01) 14(-0.003,-6.51) 15(-0.003,-7.01) 16(-0.003,-7.51) 17(-0.003,-8.01) 18(-0.003,-8.51) 19(-0.003,-9.01) 20(-0.003,-9.51) 21(-0.003,-10.01) 22(-0.003,-10.51) 23(-0.003,-11.01) 24(-0.003,-11.51) 25(-0.003,-12.01) 26(-0.003,-12.51) 27(-0.003,-13.01) 28(-0.003,-13.51) 29(7.197,-13.51) 30(7.197,-13.01) 31(7.197,-12.51) 32(7.197,-12.01) 33(7.197,-11.51) 34(7.197,-11.01) 35(7.197,-10.51) 36(7.197,-10.01) 37(7.197,-9.51) 38(7.197,-9.01) 39(7.197,-8.51) 40(7.197,-8.01) 41(7.197,-7.51) 42(7.197,-7.01) 43(7.197,-6.51) 44(7.197,-6.01) 45(7.197,-5.51) 46(7.197,-5.01) 47(7.197,-4.51) 48(7.197,-4.01) 49(7.197,-3.51) 50(7.197,-3.01) 51(7.197,-2.51) 52(7.197,-2.01) 53(7.197,-1.51) 54(7.197,-1.01) 55(7.197,-0.51) 56(7.197,-0.01)
  silkscreen extent 1.33,-13.76 5.86,0.24
ULN2803AFWG--SOIC18 [mm]
  rect 2.5x0.773 smd: 1(0,0)
  oval 2.5x0.773 smd: 2(0,-1.27) 3(0,-2.54) 4(0,-3.81) 5(0,-5.08) 6(0,-6.35) 7(0,-7.62) 8(0,-8.89) 9(0,-10.16) 10(9,-10.16) 11(9,-8.89) 12(9,-7.62) 13(9,-6.35) 14(9,-5.08) 15(9,-3.81) 16(9,-2.54) 17(9,-1.27) 18(9,0)
  silkscreen extent 1.58,-10.79 7.42,0.64
ZZ311 [mm]
  rect 1.1x1.55 smd: 1(0,0) 2(2.3,0) 3(4.6,0)
  rect 3.45x1.55 smd: 4(2.3,6.75)
  silkscreen extent -1.05,-1.45 5.65,5.22

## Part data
2.5V 3.3V 5V1 LED4 LED6 LED7 LED8 LED9 LED10 LED11: library part LED2, "Typical RED, GREEN, YELLOW, AMBER GaAs LED"
C1 C2 C3 C4 C5 C6 C7 C8 C9 C10 C11 C12 C13 C14 C15 C16 C17 C18 C19 C20 C21 C22 C24 C25 C26 C27 C28 C29 C30 C31 C32 C33 C34 C35 C36 C37 C38 C39 C40 C41 C42 C43 C44 C45 C46 C47 C48 C49 C50 C51 C52 C53 C54 C55 C56 C57 C58 C59 C60 C61 C62 C63 C64 C65 C66 C67 C68 C69 C70 C71 C72 C73 C74 C75 C76 C77 C78 C79 C80 C81: library part Cap, "Capacitor"
CP1 CP2 CP3 CP4 CP5 CP6 CP7 CP8: library part "Cap Pol3", "Polarized Capacitor (Surface Mount)"
D1: "Default Diode"
D13 D14 D15 D16: "Schottky Diode"
J1: library part "Connector 15", "Receptacle Assembly, 15-Pin, Sim Line Connector"
MAX3232_D: library part MAX3232
OSC1 OSC2: library part CRYSTAL4
P1: "Header, 3-Pin, Dual row"
P3: "Header, 2-Pin"
P6 P11: "Header, 5-Pin, Dual row"
R1 R2 R3 R4 R5 R6 R7 R8 R9 R11 R12 R13 R14 R15 R16 R17 R18 R19 R23 R25 R26: library part Res2, "Resistor"
RESET1: "Switch"
RP1 RP2 RP5 RP6: library part RESPACK8
U5: "Octal Buffer/Driver with 3-State Outputs"
U9: "EPCS16 Series, In-system programmable 3.3V serial configuration device, 16-Pin SOIC, 16-Megabit, Industrial Grade, Pb-Free"
U12: library part ULN2803A, "Darlington transistor array"
U19: "Cyclone III Family FPGA, 160 I/O Pins, 4 PLLs, 240-Pin PQFP, Speed Grade 8, Commercial Grade, Pb-Free"
U20: library part SC28L202
U23 U24: library part MAX3077E

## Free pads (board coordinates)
  round 60 hole 185.04: 0(-1,2785) 0(-1,5569) 0(0,0) 0(1594,2785) 0(1929,-407) 0(1929,5976) 0(3978,638) 0(3978,4932) 0(4803,2785)

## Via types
v1: diameter 20, hole 10, Top Layer to Bottom Layer, 184 vias
v2: diameter 40, hole 20, Top Layer to Bottom Layer, 82 vias
v3: diameter 15, hole 8, Top Layer to Bottom Layer, 11 vias
v4: diameter 60, hole 30, Top Layer to Bottom Layer, 8 vias
v5: diameter 30, hole 15, Top Layer to Bottom Layer, 2 vias

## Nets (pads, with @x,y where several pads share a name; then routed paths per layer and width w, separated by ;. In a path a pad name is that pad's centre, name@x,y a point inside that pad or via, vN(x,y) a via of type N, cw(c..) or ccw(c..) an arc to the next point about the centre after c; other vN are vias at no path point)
1.2V: C33.2 C34.2 C35.2 C36.2 C37.2 C38.2 C39.2 C40.2 C41.2 C42.2 C43.2 C44.2 C45.2 CP4.1 CP7.1 F1.2 U13.2 U13.4 U19.10 U19.40 U19.53 U19.61 U19.74 U19.115 U19.129 U19.140 U19.163 U19.190 U19.204 U19.228 | length 2154.3
  Top Layer w10: U19.163@1786.61,1643.94 v1(1868.94,1643.94) ; U19.140@1786.61,2096.69 v1(1870.31,2096.69) ; U19.129@1786.61,2313.23 v1(1871.77,2313.23) ; v1(1967.72,2471.72) U19.115@1967.72,2553.39 ; U19.190@2046.46,1226.61 v1(2046.46,1309.46) ; U19.204@2322.05,1226.61 v1(2322.05,1308.95) ; v1(2774.8,2470.2) U19.74@2774.8,2553.39 ; U19.228@2794.49,1226.61 v1(2794.49,1309.49) ; v1(3030.71,2472.29) U19.61@3030.71,2553.39 ; v1(3030.91,2332.91) U19.53@3113.39,2332.91 ; v1(3031.46,1486.46) U19.10@3113.39,1486.46 ; v1(3031.99,2077.01) U19.40@3113.39,2077.01
  Top Layer w30: C33.2@2643,645.44 2643.31,645.75 U13.4@2781.55,645.75
  Top Layer w40: U13.2@2781.55,380 U13.4@2781.55,645.75 2829,693.2 v4(2829,743)
  Bottom Layer w10: v1(1868.94,1643.94) 1869,1644 C38.2@1913.44,1644 ; v1(1870.31,2096.69) C39.2@1913.13,2096.69 ; v1(1871.77,2313.23) 1872,2313 C40.2@1913.44,2313 ; C41.2@1967.72,2430.84 v1(1967.72,2471.72) ; v1(2046.46,1309.46) C34.2@2046.46,1349.98 ; v1(2322.05,1308.95) C35.2@2322.05,1349.49 ; C42.2@2774.8,2430.76 v1(2774.8,2470.2) ; C36.2@2782.68,1353 2794.49,1341.19 v1(2794.49,1309.49) ; C45.2@2983,2067.56 2992.45,2077.01 v1(3031.99,2077.01) ; C37.2@2989,1511.44 3013.98,1486.46 v1(3031.46,1486.46) v1@3031,1486 ; C44.2@2991.65,2332.91 v1(3030.91,2332.91) ; C43.2@3030.71,2428.74 v1(3030.71,2472.29)
  Bottom Layer w40: CP4.1@2826.85,630 2829,632.15 v4(2829,743)
  other v2: 2822,958
2.5V: 2.5V.1 C49.2 C52.2 C58.2 C59.2 C60.2 CP6.1 P6.4 U17.2 U17.4 U19.3 U19.58 U19.123 U19.178 | length 2820.1
  Top Layer w10: U19.178@1786.61,1348.66 1928.66,1348.66 v1(1990,1410) ; U19.123@1786.61,2431.34 1985.66,2431.34 v1(2052,2365) ; v1(2860,2365) 2926.34,2431.34 U19.58@3113.39,2431.34 ; v1(2920,1429) 3000.34,1348.66 U19.3@3113.39,1348.66
  Top Layer w30: 2.5V.1@2828,220 3063,220 3174.55,331.55 U17.2@3174.55,380 ; C49.2@3172.44,720 3172.44,1038.44 3217,1083 3294,1083 P6.4@3362,1015 ; U17.4@3174.55,645.75 C49.2@3174.55,717.89
  Top Layer w40: v4@3048.75,645.75 U17.4@3174.55,645.75 U17.2@3174.55,380
  Bottom Layer w10: v1(1990,1410) C52.2@1990,1469.44 ; C58.2@2052,2316.56 v1(2052,2365) ; C59.2@2860,2316.56 v1(2860,2365)
  Bottom Layer w40: v4(3048,645) 3201.85,645 CP6.1@3216.85,630
3.3V: 3.3V.1 C2.2 C4.2 C6.2 C8.2 C10.2 C12.2 C15.2 C17.2 C19.2 C21.2 C22.2 C31.2 C46.1 C47.1 C50.2 C51.2 C53.2 C54.1 C55.1 C56.2 C57.1 C65.2 C66.2 C67.2 C68.2 C69.2 C70.2 C71.2 C72.2 C73.2 C74.2 C75.2 C76.2 C77.2 C78.2 C79.2 C80.2 CP2.1 D1.2 D13.2 D14.2 D15.2 D16.2 MAX3232_D.16 OSC1.4 OSC2.4 P11.4 R1.1 R2.2 R3.2 R4.2 R5.2 R12.2 R13.2 R14.2 R15.2 R16.2 R17.2 R18.1 R19.2 RP5.1 RP5.2 RP5.3 RP5.4 RP6.1 RP6.2 RP6.3 RP6.4 U2.10 U2.16 U3.10 U3.16 U4.10 U4.16 U6.10 U6.16 U7.10 U7.16 U8.10 U8.16 U9.1 U9.2 U9.9 U11.2 U11.4 U14.1 U15.1 U16.1 U19.7 U19.15 U19.35 U19.47 U19.66 U19.77 U19.96 U19.104 U19.124 U19.136 U19.154 U19.157 U19.170 U19.192 U19.206 U19.213 U19.225 U20.1 U20.13 U20.27 U20.41 U20.42 U23.1 U24.1 | length 8757.4
  Top Layer w10: C50.2@1034.56,835 1049,835 1067.81,816.19 U20.27@1067.81,750.1 ; C53.2@1284.35,391.91 U20.41@1284.35,466.64 U20.42@1304.03,466.64 ; C57.1@1320,832.44 1343.4,809.04 U20.13@1343.4,750.1 ; U20.1@1579.62,750.1 1648.56,819.04 C56.2@1648.56,832 ; C66.2@1698.66,1821.1 U19.154@1786.61,1821.1 1738.9,1821.1 ; C68.2@1698.91,2411.65 U19.124@1786.61,2411.65 ; v1(1717.05,1762.05) U19.157@1786.61,1762.05 ; v3(1726.14,1506.14) U19.170@1786.61,1506.14 ; v3(1726.57,2175.43) U19.136@1786.61,2175.43 ; v3(2085.83,1171) U19.192@2085.83,1226.61 ; U19.104@2184.25,2553.39 v3(2184.25,2611.75) ; v1(2327,2612.73) 2341.73,2598 U19.96@2341.73,2553.39 ; v3(2361.42,1166.58) U19.206@2361.42,1226.61 ; v1(2484,1171) 2499.21,1186.21 U19.213@2499.21,1226.61 ; U19.77@2715.75,2553.39 v3(2715.75,2610.75) ; U19.225@2735.43,1226.61 2735.43,1147.01 C69.2@2746.44,1136 ; C74.2@2926,2641.44 2932.28,2635.16 U19.66@2932.28,2553.39 ; C74.2@2926,2652.44 C74.2@2932.28,2646.16 ; U19.7@3113.39,1427.4 3158.04,1427.4 C80.2@3194.44,1391 ; U19.15@3113.39,1584.88 3176.32,1584.88 C79.2@3194.44,1603 ; U19.35@3113.39,1978.58 C78.2@3193.86,1978.58 ; U19.47@3113.39,2214.8 v3(3172.8,2214.8)
  Top Layer w20: U23.1@800,850 843,893 1000,893 1034.56,858.44 C50.2@1034.56,835 ; RP6.1@1108,230.29 RP6.2@1145,230.29 RP6.3@1177,230.29 RP6.4@1213,230.29 1251.29,230.29 v2(1282.44,261.44) C51.2@1282.44,330 C53.2@1282.44,390 ; v1(1856,4221) U3.10@1924.02,4221 ; v1(1862,3759) U2.10@1924.02,3759 ; v1(2530,3896) U8.10@2597.02,3896 ; U4.10@2597.02,3427 v1(2654,3427) ; v2(3475,1373) U9.9@3475,1302.83 3475,1236 v2(3508,1203) ; U9.2@3775,1657.17 U9.1@3825,1657.17 v2(3886.17,1657.17) ; U6.10@3988.02,3697 v1(4054,3697) ; U7.10@3988.02,4143 v1(4054,4143)
  Top Layer w30: v2(542,274) OSC2.4@650,166 ; v2(713,1609) OSC1.4@788,1534 ; MAX3232_D.16@845,2117 v5(913,2117) ; v2(1852,4062) 1855,4059 U2.16@1924.02,4059 ; v2(1853,4523) 1855,4521 U3.16@1924.02,4521 ; R19.2@2002,283.56 2002,352 2295.75,645.75 U11.4@2379.55,645.75 ; v4(2380,734) 2467.44,734 C31.2@2468.44,733 ; v2(2525,4196) U8.16@2597.02,4196 ; v2(2529,3727) U4.16@2597.02,3727 ; v2(3215,2848) 3216.56,2849.56 C19.2@3216.56,2903 ; R3.2@3514.56,725 v2(3576,725) ; v2(3919,4442) 3920,4443 U7.16@3988.02,4443 ; U14.1@3986,2747 v2(4052,2747) ; U15.1@3987,3197 4052,3197 v2(4053,3196) ; U6.16@3988.02,3997 v2(4053,3997)
  Top Layer w40: U11.2@2379.55,370.45 U11.2@2379.55,380 ; v4(2380,734) 2379.55,733.55 U11.4@2379.55,645.75 U11.2@2379.55,380 ; 3.3V.1@2546,214 3.3V.1@2546,220 2546,268 2502,312 2447.55,312 U11.2@2379.55,380
  Bottom Layer w10: C65.2@1680.7,1506.14 v3(1726.14,1506.14) ; C67.2@1680.99,2175.43 v3(1726.57,2175.43) ; C72.2@2085.83,1121.27 v3(2085.83,1171) ; v3(2184.25,2611.75) C76.2@2184.25,2654.19 ; v1(2327,2612.73) 2327,2646.44 C75.2@2335,2654.44 ; C71.2@2361.42,1121.14 v3(2361.42,1166.58) ; v1(2484,1171) 2484,1136.56 C70.2@2499.56,1121 ; v3(2715.75,2610.75) C73.2@2715.75,2655.6 ; v3(3172.8,2214.8) C77.2@3216.64,2214.8
  Bottom Layer w20: C54.1@710,432.44 732.44,410 U24.1@800,410 ; C55.1@710,872.44 732.44,850 U23.1@800,850 ; v2(1746,300) RP5.4@1746,364.29 RP5.3@1782,364.29 RP5.2@1814,364.29 RP5.1@1851,364.29 1893.52,406.81 D1.2@2009.22,406.81 ; v2(3886.17,1657.17) 3927.44,1698.44 R4.2@3937,1698.44
  Bottom Layer w30: v2(542,274) 657,274 719.44,211.56 C46.1@719.44,90 ; v2(713,1609) 793,1609 862.44,1539.56 C47.1@862.44,1457 ; v5(913,2117) C22.2@971.56,2117 ; C4.2@1793,4057.56 1797.44,4062 v2(1852,4062) ; C2.2@1793,4520.56 1795.44,4523 v2(1853,4523) ; D1.2@2009.22,406.81 2114.81,406.81 2332,624 CP2.1@2422.85,624 ; C6.2@2470,4197.56 2471.56,4196 v2(2525,4196) ; C8.2@2475,3729.56 2477.56,3727 v2(2529,3727) ; v2(3215,2848) 3216,2847 U16.1@3216,2776 ; v2(3576,725) 3607.44,756.44 R2.2@3607.44,793 ; C10.2@3860,4445.56 3863.56,4442 v2(3919,4442) ; v2(4052,2747) 4057.56,2741.44 C17.2@4105,2741.44 ; v2(4053,3196) 4057.56,3191.44 C15.2@4109,3191.44 ; v2(4053,3997) 4110.56,3997 C12.2@4111,3996.56
  Bottom Layer w40: v4(2380,734) 2422.85,691.15 CP2.1@2422.85,624 ; R16.2@4537.4,2479 4537.4,2597.4 4538,2598 4538,2832 v2(4538,3047)
  other v1: 1305,842 1661,845 1174,920 2743,1122 3184,1380 3180,1612 3239,1680 4329,1752 1691,1833 3186,1965 721,2143 4458,2270 1705,2425 2938,2650
  other v2: 4002,1088 3431,1961
5V: C1.2 C3.2 C5.2 C7.2 C9.2 C11.2 C13.2 C14.2 C16.2 C18.2 J2.17 J5.3 R23.2 RP1.1 RP1.2 RP1.3 RP1.4 RP2.1 RP2.2 RP2.3 RP2.4 U2.1 U3.1 U4.1 U5.20 U6.1 U7.1 U8.1 U14.10 U14.16 U15.10 U15.16 U16.10 U16.16 | length 2428.1
  Top Layer w10: U8.1@2221.71,4197.29 v1(2221.71,4256.71) ; U4.1@2223,3727 v1@2223,3802.42
  Top Layer w20: R23.2@1248.44,5401 1194,5455.44 1194,5645.12 J5.3@1288.83,5739.95 ; U14.10@3611.98,3047 v1(3685,3047) ; U15.10@3612.98,3497 v1(3686,3497)
  Top Layer w30: U2.1@1550,4059 v2(1622,4059) ; U3.1@1550,4521 v2(1621,4521) ; U4.1@2223,3727 v2(2295,3727) ; U8.1@2223,4196 v2(2296,4196) ; C3.2@3215.56,3023 3216,3023.44 v2(3216,3078) ; U14.16@3611.98,2747 3679,2747 v2(3680,2746) ; U15.16@3612.98,3197 3683,3197 v2(3684,3198) ; U6.1@3614,3997 v2(3687,3997) ; U7.1@3614,4443 v2(3684,4443)
  Bottom Layer w10: RP2.1@2038,3804.71 RP2.2@2075,3804.71 RP2.3@2107,3804.71 RP2.4@2143,3804.71 v1(2220.71,3804.71) ; RP1.1@2050,4256.71 RP1.2@2087,4256.71 RP1.3@2119,4256.71 RP1.4@2155,4256.71 v1(2221.71,4256.71)
  Bottom Layer w20: v1(2916,3072) U16.10@2916,3150.02
  Bottom Layer w30: v2(1621,4521) C1.2@1676.56,4521 ; v2(1622,4059) 1678.56,4059 C5.2@1680,4057.56 ; v2(2295,3727) 2347.44,3727 C9.2@2348,3727.56 ; v2(2296,4196) C7.2@2353.44,4196 ; v2(3216,3078) U16.16@3216,3150.02 ; U5.20@3218,3627.94 C13.2@3218,3768.44 ; v2(3680,2746) 3682.56,2743.44 C18.2@3744,2743.44 ; v2(3684,3198) C16.2@3747.44,3198 ; v2(3684,4443) 3745.44,4443 C11.2@3747,4444.56 ; v2(3687,3997) C14.2@3745.44,3997
  other v2: 3218,3692
5V1: 5V1.1 C30.2 C32.2 C48.2 CP1.1 CP3.1 CP5.1 J1.11 J1.12 J1.13 U11.3 U13.3 U17.3 | length 457.3
  Top Layer w30: U11.3@2470.1,380 2477.66,372.44 C30.2@2560,372.44 ; U13.3@2872.1,380 2879.66,372.44 C32.2@2960,372.44 ; U17.3@3265.1,380 3272.66,372.44 C48.2@3350,372.44
  Top Layer w40: U11.3@2470.1,380 v2@2470.1,439.9 ; U13.3@2872.1,380 2872.1,432.1 v2(2880,440) ; U17.3@3265.1,380 3265.1,435.1 v2(3270,440)
  other v2: 2273,242 2470,440
+ASX: J2.6 U6.4 | length 1161.7
  Top Layer w8: J2.6@2897.76,4651.69 2897.76,4627.24 2973,4552 3023,4552 3478.5,4096.5 3478.5,3929.5 3561,3847 U6.4@3614,3847
+ASY: J2.4 U7.6 | length 798.3
  Top Layer w8: J2.4@2986.86,4606.29 3106.71,4606.29 3520,4193 U7.6@3614,4193
+ASZ: J2.2 U6.3 | length 914.3
  Top Layer w8: J2.2@3075.96,4560.9 3520,4116.85 3520,3944 3567,3897 U6.3@3614,3897
+LAX: J2.23 U2.3 | length 1778.3
  Top Layer w8: U2.3@1550,3959 1496,3959 1473,3982 1473,4180 1406,4247 1406,4682 1850.69,5126.69 J2.23@2185.8,5126.69
+LAY: J2.21 U3.6 | length 1488.3
  Top Layer w8: U3.6@1550,4271 1475,4271 1436,4310 1436,4651 1866.29,5081.29 J2.21@2274.9,5081.29
+LAZ: J2.19 U2.5 | length 2678.4
  Top Layer w8: U2.5@1550,3859 1493,3859 1409,3943 1409,4131 1342,4198 1342,4935 1827,5420 2152,5420 2364,5208 J2.19@2364,5035.89
-ASX: J2.5 U7.3 | length 1051.2
  Top Layer w8: J2.5@2987.71,4718.09 3089.61,4820 3398,4820 3536,4682 3536,4366 3559,4343 U7.3@3614,4343
-ASY: J2.3 U7.4 | length 918.2
  Top Layer w8: J2.3@3076.81,4672.7 3153.11,4749 3379,4749 3504,4624 3504,4350 3561,4293 U7.4@3614,4293
-ASZ: J2.1 U7.5 | length 616.2
  Top Layer w8: J2.1@3165.91,4627.3 3165.91,4612.09 3535,4243 U7.5@3614,4243
-LAX: J2.22 U3.5 | length 1251.3
  Top Layer w8: U3.5@1550,4321 1497,4321 1462,4356 1462,4617 1859.89,5014.89 J2.22@2184.95,5014.89
-LAY: J2.20 U3.4 | length 1166.2
  Top Layer w8: U3.4@1519,4371 1491,4399 1491,4582 1878.49,4969.49 J2.20@2274.05,4969.49
-LAZ: J2.18 U2.4 | length 2610.1
  Top Layer w8: U2.4@1550,3909 1493,3909 1443,3959 1443,4150 1375,4218 1375,4907 1850,5382 2130,5382 2321,5191 2321,4966.24 J2.18@2363.15,4924.09
A0: U19.182 U20.25 | length 1200.4
  Top Layer w8: U20.25@1107.18,750.1 1107.18,1077.18 1174.13,1144.13 1857.13,1144.13 1888.98,1175.98 U19.182@1888.98,1226.61
A1: U19.183 U20.24 | length 1196.9
  Top Layer w8: U20.24@1126.87,750.1 1126.87,1066.87 1188.25,1128.25 1865.25,1128.25 1906.76,1169.76 1906.76,1224.71 U19.183@1908.66,1226.61
A2: U19.184 U20.23 | length 1194
  Top Layer w8: U20.23@1146.55,750.1 1146.55,1056.55 1200,1110 1872,1110 1928.35,1166.35 U19.184@1928.35,1226.61
A2A: J1.5 R25.1 U23.8 | length 287.6
  Top Layer w20: J1.5@350,942.44 442.44,850 U23.8@500,850
  Bottom Layer w20: U23.8@500,850 567.56,850 R25.1@590,872.44
A2B: J1.6 R25.2 U23.7 | length 295.1
  Top Layer w20: J1.6@350,1060.55 460.55,950 U23.7@500,950
  Bottom Layer w20: U23.7@500,950 567.56,950 R25.2@590,927.56
A2Y: J1.8 U23.5 | length 207.6
  Top Layer w20: J1.8@353.23,1296.77 U23.5@500,1150
A2Z: J1.7 U23.6 | length 203.3
  Top Layer w8: U23.6@478.66,1050 U23.6@500,1050
  Top Layer w20: J1.7@350,1178.66 U23.6@478.66,1050
A3: U19.198 U20.6 | length 1013.5
  Top Layer w8: U20.6@1481.2,750.1 1481.2,853.2 1546.25,918.25 1951.9,918.25 2203.94,1170.28 U19.198@2203.94,1226.61
A4: U19.199 U20.5 | length 1013.5
  Top Layer w8: U20.5@1500.88,750.1 1500.88,850.43 1552.83,902.38 1958.48,902.38 2223.62,1167.52 U19.199@2223.62,1226.61
A5: U19.200 U20.4 | length 1013.5
  Top Layer w8: U20.4@1520.57,750.1 1520.57,847.67 1559.4,886.5 1965.05,886.5 2243.31,1164.76 U19.200@2243.31,1226.61
A6: U19.201 U20.3 | length 1013.5
  Top Layer w8: U20.3@1540.25,750.1 1540.25,844.9 1565.35,870 1971,870 2262.99,1161.99 U19.201@2262.99,1226.61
